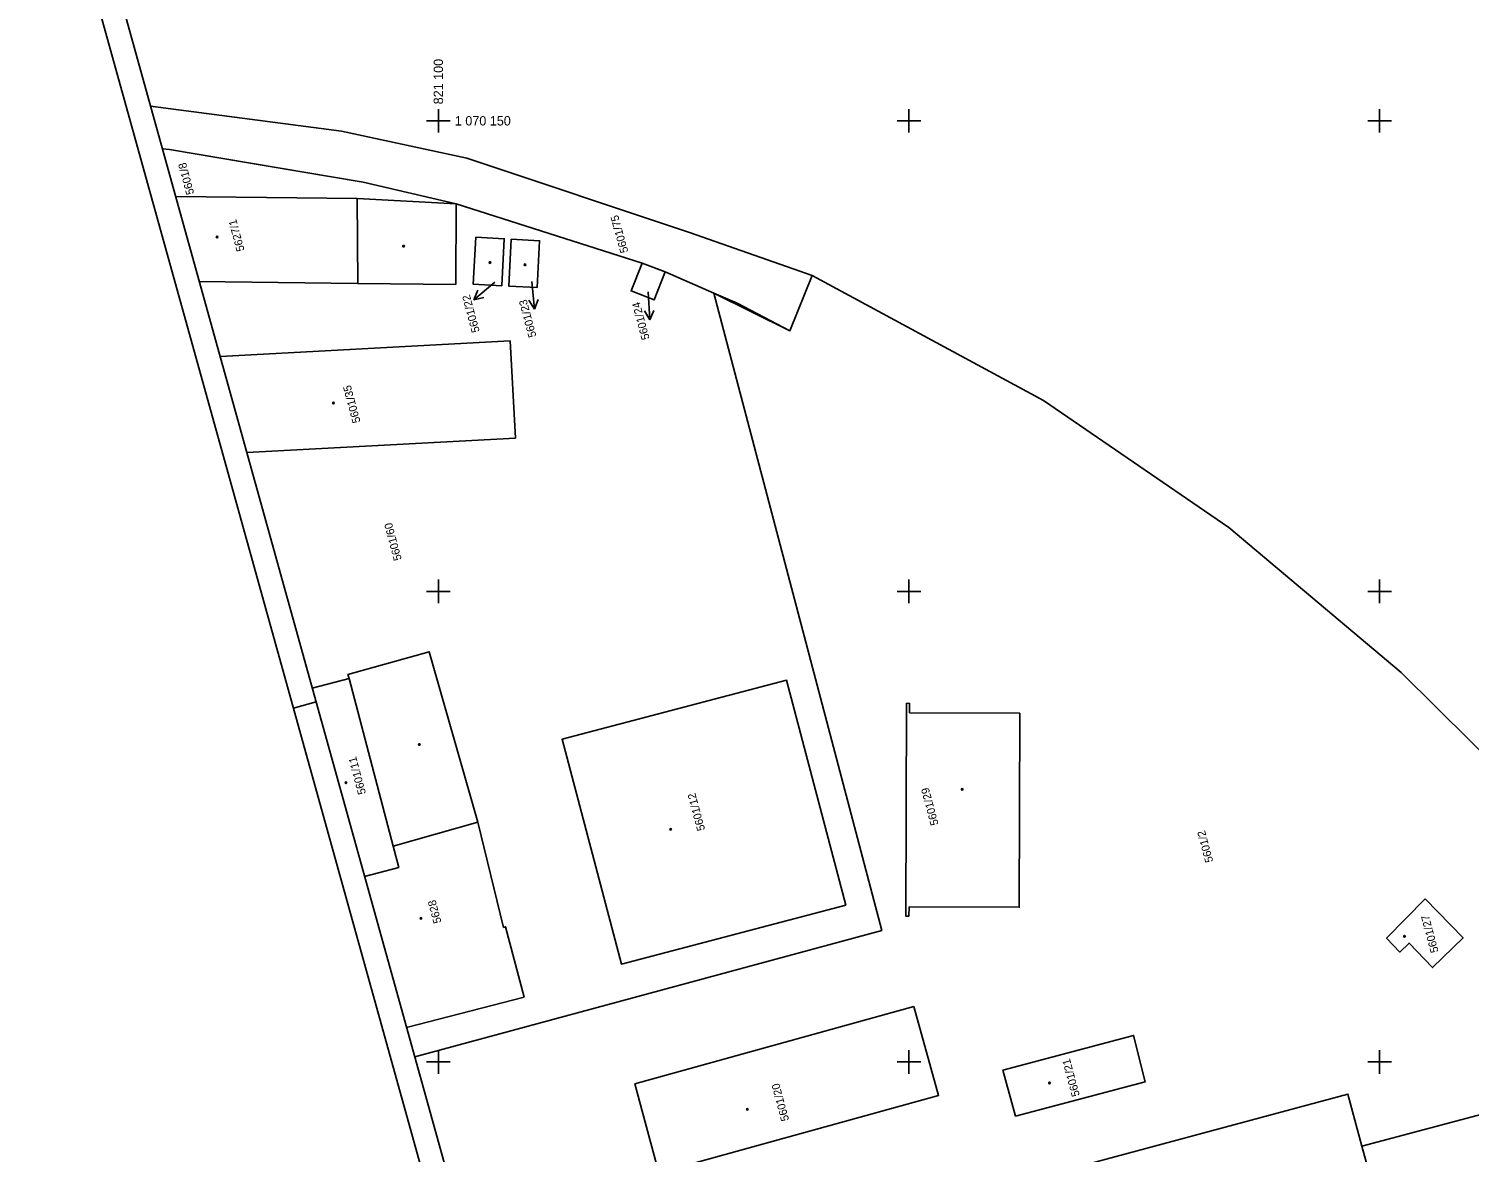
# Model space of a CAD drawing. Extents: x -821172 to -820632, y -1070921 to -1069931.
# Drawn here: x -821143.5 to -820990.5, y -1070259.6 to -1070140.2 of the extents above; entities that cross this region are included whole.
import ezdxf

# ---------------------------------------------------------------- set-up
doc = ezdxf.new("R2010")
doc.units = 0
for name, color, linetype in [('Ram', 7, 'Continuous'), ('Sit', 7, 'Continuous'), ('Vrstva 53', 7, 'Continuous'), ('Vrstva 55', 7, 'Continuous'), ('Vrstva 56', 7, 'Continuous'), ('Vrstva 57', 7, 'Continuous'), ('Vrstva 59', 7, 'Continuous')]:
    doc.layers.add(name, color=color, linetype=linetype)

msp = doc.modelspace()

# ---------------------------------------------------------------- linework, layer by layer
at = {"layer": 'Ram'}
msp.add_line((-821112.99, -1070211.73), (-821115.4, -1070212.4), dxfattribs=at)
msp.add_line((-821112.99, -1070211.73), (-821115.4, -1070212.4), dxfattribs=at)
for points in [[(-820775.54, -1070880.81), (-820918.62, -1070920.57), (-821143.51, -1070111.23)], [(-820916.88, -1070917.49), (-821140.43, -1070112.97)]]:
    msp.add_lwpolyline(points, dxfattribs=at)
at = {"layer": 'Sit'}
for p, q in [((-821100, -1070148.75), (-821100, -1070150)), ((-821050, -1070148.75), (-821050, -1070150)), ((-821000, -1070148.75), (-821000, -1070150)), ((-821101.25, -1070150), (-821100, -1070150)), ((-821098.75, -1070150), (-821100, -1070150)), ((-821100, -1070151.25), (-821100, -1070150)), ((-821051.25, -1070150), (-821050, -1070150)), ((-821048.75, -1070150), (-821050, -1070150)), ((-821050, -1070151.25), (-821050, -1070150)), ((-821001.25, -1070150), (-821000, -1070150)), ((-820998.75, -1070150), (-821000, -1070150)), ((-821000, -1070151.25), (-821000, -1070150)), ((-821100, -1070198.75), (-821100, -1070200)), ((-821050, -1070198.75), (-821050, -1070200)), ((-821000, -1070198.75), (-821000, -1070200)), ((-821101.25, -1070200), (-821100, -1070200)), ((-821098.75, -1070200), (-821100, -1070200)), ((-821100, -1070201.25), (-821100, -1070200)), ((-821051.25, -1070200), (-821050, -1070200)), ((-821048.75, -1070200), (-821050, -1070200)), ((-821050, -1070201.25), (-821050, -1070200)), ((-821001.25, -1070200), (-821000, -1070200)), ((-820998.75, -1070200), (-821000, -1070200)), ((-821000, -1070201.25), (-821000, -1070200)), ((-821101.25, -1070250), (-821100, -1070250)), ((-821100, -1070248.75), (-821100, -1070250)), ((-821098.75, -1070250), (-821100, -1070250)), ((-821100, -1070251.25), (-821100, -1070250)), ((-821051.25, -1070250), (-821050, -1070250)), ((-821050, -1070248.75), (-821050, -1070250)), ((-821048.75, -1070250), (-821050, -1070250)), ((-821050, -1070251.25), (-821050, -1070250)), ((-821001.25, -1070250), (-821000, -1070250)), ((-821000, -1070248.75), (-821000, -1070250)), ((-820998.75, -1070250), (-821000, -1070250)), ((-821000, -1070251.25), (-821000, -1070250))]:
    msp.add_line(p, q, dxfattribs=at)
at = {"layer": 'Vrstva 53'}
for points in [[(-821060.28, -1070166.43), (-821062.65, -1070172.3), (-821070.73, -1070168.3), (-821075.91, -1070166.06), (-821078.33, -1070165.11), (-821098.1, -1070158.83), (-821108, -1070156.52), (-821118.28, -1070154.79), (-821128.56, -1070153.06), (-821129.31, -1070152.99)], [(-820959.73, -1070254.91), (-820961.88, -1070251.33), (-820966.49, -1070244.53), (-820975.99, -1070231.76), (-820986.52, -1070219.72), (-820997.71, -1070208.62), (-821016.02, -1070193.21), (-821035.7, -1070179.73), (-821060.28, -1070166.43)]]:
    msp.add_lwpolyline(points, dxfattribs=at)
at = {"layer": 'Vrstva 55'}
for p, q in [((-821078.33, -1070165.11), (-821098.1, -1070158.83)), ((-821075.91, -1070166.06), (-821078.33, -1070165.11)), ((-821070.73, -1070168.3), (-821075.91, -1070166.06))]:
    msp.add_line(p, q, dxfattribs=at)
for points in [[(-821130.57, -1070148.44), (-821110.29, -1070151.09), (-821096.97, -1070153.98), (-821073.33, -1070161.88), (-821060.28, -1070166.43)], [(-821098.1, -1070158.83), (-821108, -1070156.52), (-821128.56, -1070153.06), (-821129.31, -1070152.99)], [(-821127.9, -1070158.05), (-821108.61, -1070158.27), (-821098.1, -1070158.83)], [(-821125.39, -1070167.09), (-821122.63, -1070167.12), (-821108.55, -1070167.27), (-821098.15, -1070167.39), (-821098.1, -1070158.83)], [(-821096.03, -1070162.37), (-821096.3, -1070167.37), (-821093.26, -1070167.53), (-821093, -1070162.53), (-821096.03, -1070162.37)], [(-821092.25, -1070162.57), (-821092.52, -1070167.57), (-821089.51, -1070167.73), (-821089.24, -1070162.74), (-821092.25, -1070162.57)], [(-821078.33, -1070165.11), (-821079.53, -1070168.08), (-821077.08, -1070169.04), (-821075.91, -1070166.06)], [(-821060.28, -1070166.43), (-821062.65, -1070172.3), (-821068.26, -1070169.37), (-821070.73, -1070168.3)], [(-821060.28, -1070166.43), (-821035.7, -1070179.73), (-821016.02, -1070193.21), (-820997.71, -1070208.62), (-820986.52, -1070219.72), (-820975.99, -1070231.76), (-820966.49, -1070244.53), (-820961.88, -1070251.33), (-820959.73, -1070254.91)], [(-821070.73, -1070168.3), (-821052.89, -1070236.05), (-821102.51, -1070249.45)], [(-821120.34, -1070185.26), (-821091.82, -1070183.72), (-821092.38, -1070173.39), (-821123.18, -1070175.06)], [(-821095.81, -1070224.51), (-821100.98, -1070206.42), (-821109.6, -1070208.83), (-821109.49, -1070209.25), (-821113.39, -1070210.28)], [(-821056.71, -1070233.33), (-821063, -1070209.44), (-821086.85, -1070215.72), (-821080.56, -1070239.61), (-821056.71, -1070233.33)], [(-821038.22, -1070212.93), (-821038.29, -1070233.56), (-821049.98, -1070233.51), (-821050, -1070234.51), (-821050.33, -1070234.52), (-821050.26, -1070211.89), (-821049.93, -1070211.9), (-821049.94, -1070212.89), (-821038.22, -1070212.93)], [(-821107.83, -1070230.3), (-821104.21, -1070229.35), (-821104.8, -1070227.09), (-821095.81, -1070224.51)], [(-821103.37, -1070246.35), (-821090.89, -1070243.13), (-821092.86, -1070235.63), (-821093.07, -1070235.71), (-821095.81, -1070224.51)], [(-820995.15, -1070232.68), (-820991.13, -1070236.82), (-820994.37, -1070239.98), (-820996.87, -1070237.37), (-820997.84, -1070238.33), (-820999.26, -1070236.86), (-820995.15, -1070232.68)], [(-821049.48, -1070244.11), (-821046.85, -1070253.56), (-821076.58, -1070261.77), (-821079.11, -1070252.34), (-821049.48, -1070244.11)], [(-821040.02, -1070250.86), (-821026.15, -1070247.18), (-821024.9, -1070252.11), (-821038.68, -1070255.76), (-821040.02, -1070250.86)], [(-821001.88, -1070258.94), (-821003.37, -1070253.41), (-821041.15, -1070263.6)], [(-820983.06, -1070258.22), (-820987.52, -1070255.14), (-821001.88, -1070258.94)], [(-821001.88, -1070258.94), (-821000.98, -1070262.27), (-821006.88, -1070263.86)]]:
    msp.add_lwpolyline(points, dxfattribs=at)
at = {"layer": 'Vrstva 56'}
for p, q in [((-821108.61, -1070158.27), (-821108.55, -1070167.27)), ((-821104.8, -1070227.09), (-821109.49, -1070209.25))]:
    msp.add_line(p, q, dxfattribs=at)
at = {"layer": 'Vrstva 57'}
for p, q in [((-821093.99, -1070167.13), (-821096.24, -1070169.02)), ((-821090.06, -1070167.07), (-821089.8, -1070170)), ((-821096.24, -1070169.02), (-821095.81, -1070168.01)), ((-821096.24, -1070169.02), (-821095.18, -1070168.77)), ((-821089.8, -1070170), (-821090.38, -1070169.06)), ((-821089.8, -1070170), (-821089.4, -1070168.98)), ((-821077.7, -1070168.19), (-821077.55, -1070171.16)), ((-821077.55, -1070171.16), (-821078.09, -1070170.19)), ((-821077.55, -1070171.16), (-821077.1, -1070170.14))]:
    msp.add_line(p, q, dxfattribs=at)
at = {"layer": 'Vrstva 59'}
for centre in [(-821123.5, -1070162.34), (-821103.7, -1070163.32), (-821094.51, -1070165.06), (-821090.79, -1070165.3), (-821111.14, -1070179.98), (-821102.02, -1070216.27), (-821109.81, -1070220.33), (-821044.35, -1070221.04), (-821075.32, -1070225.29), (-821101.84, -1070234.74), (-820997.36, -1070236.65), (-821035.07, -1070252.24), (-821067.17, -1070255.03)]:
    msp.add_circle(centre, 0.0875, dxfattribs=at)

# ---------------------------------------------------------------- texts
at = {"layer": 'Sit'}
msp.add_text('821 100', height=1, rotation=90, dxfattribs=at).set_placement((-821099.5, -1070148.25))
msp.add_text('1 070 150', height=1, dxfattribs=at).set_placement((-821098.25, -1070150.5))
at = {"layer": 'Vrstva 57'}
for s, rotation, p in [('5601/8', 105, (-821125.93, -1070157.73)), ('5627/1', 105, (-821120.58, -1070163.76)), ('5601/75', 105.5289, (-821079.81, -1070163.91)), ('5601/22', 105, (-821095.6, -1070172.38)), ('5601/23', 105, (-821089.57, -1070172.89)), ('5601/24', 105, (-821077.55, -1070173.15)), ('5601/35', 105, (-821108.26, -1070181.99)), ('5601/60', 105, (-821103.88, -1070196.61)), ('5601/11', 105, (-821107.68, -1070221.46)), ('5601/29', 105, (-821046.85, -1070224.75)), ('5601/12', 105, (-821071.65, -1070225.32)), ('5601/2', 105, (-821017.67, -1070228.69)), ('5628', 105, (-821099.66, -1070235.16)), ('5601/27', 105, (-820993.73, -1070238.28)), ('5601/21', 105, (-821031.85, -1070253.56)), ('5601/20', 105, (-821062.73, -1070256.17))]:
    msp.add_text(s, height=0.85, rotation=rotation, dxfattribs=at).set_placement(p)

doc.saveas('drawing.dxf')
